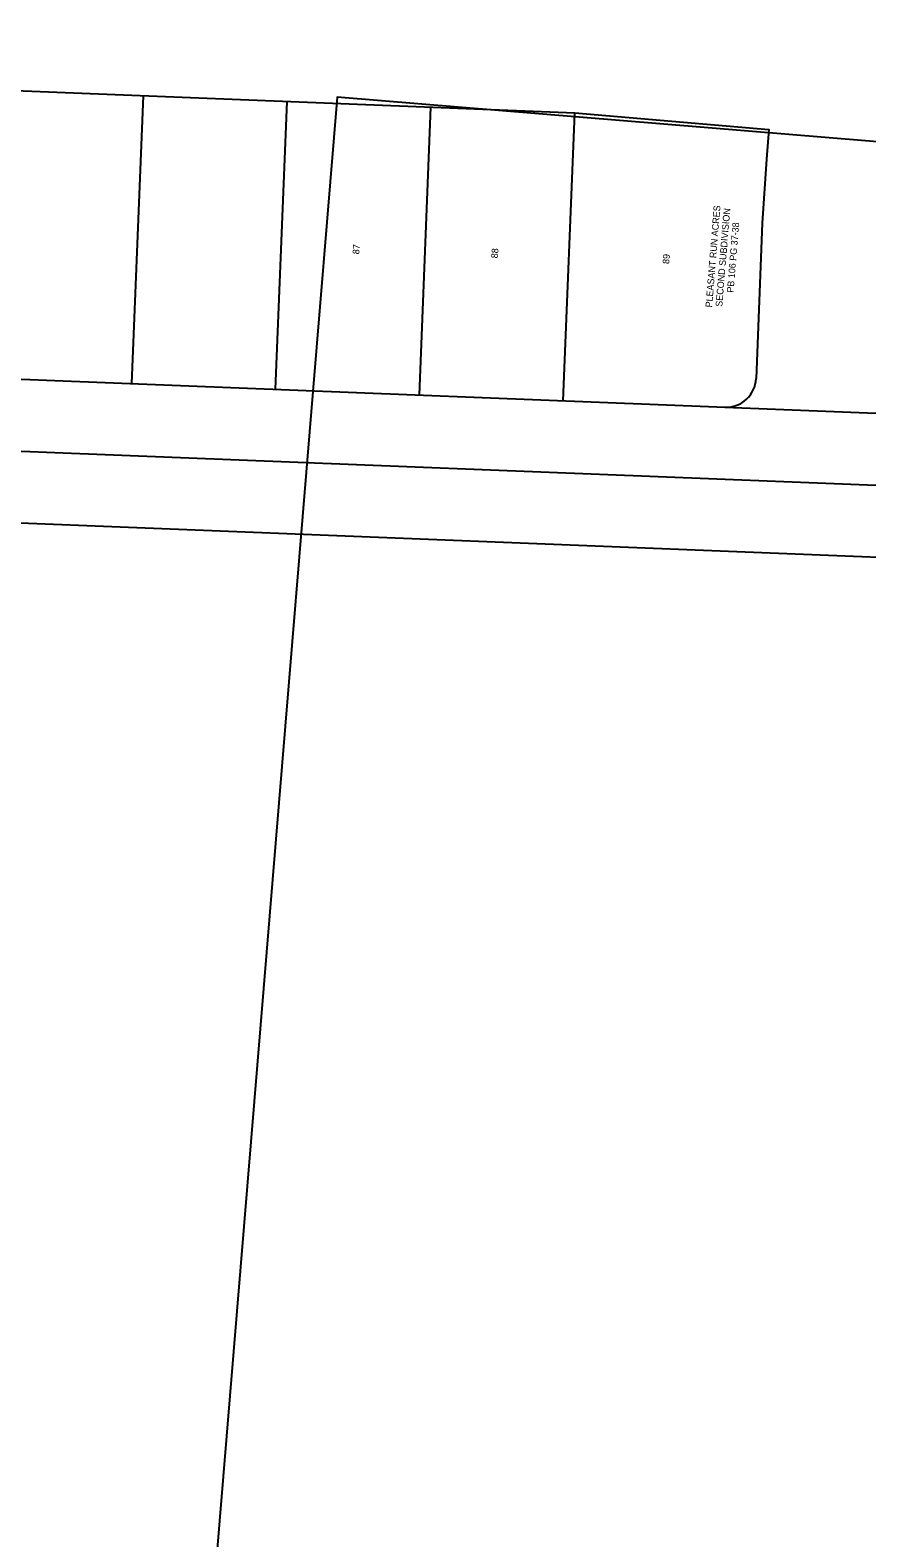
# Model space of a CAD drawing. Extents: x 1379776 to 1382941, y 467490 to 471592.
# Drawn here: x 1381007 to 1381356, y 469835 to 470463 of the extents above; entities that cross this region are included whole.
import ezdxf

# ---------------------------------------------------------------- set-up
doc = ezdxf.new("R2010")
doc.units = 0
for name, color, linetype in [('PV_P_Drive', 7, 'Continuous'), ('PV_X_Driveway', 7, 'Continuous'), ('RC_X_Text', 7, 'Continuous'), ('RD_X_Wall', 7, 'Continuous'), ('SH_Named_Boundary', 7, 'Continuous'), ('SV_X_Break_Lines', 7, 'Continuous')]:
    doc.layers.add(name, color=color, linetype=linetype)

msp = doc.modelspace()

# ---------------------------------------------------------------- linework, layer by layer
at = {"layer": 'PV_P_Drive'}
msp.add_line((1380559.29, 470305.26), (1381622.42, 470262.79), dxfattribs=at)
msp.add_lwpolyline([(1380244.81, 470361.47), (1380249.52, 470458.85), (1380334.42, 470454.75), (1380369.86, 470462.95), (1381233.96, 470428.43), (1381314.91, 470421.56), (1381313.86, 470409.15), (1381312.19, 470382.46), (1381309.61, 470317.82)], dxfattribs=at)
msp.add_arc((1381297.12, 470318.32), 12.5, 267.71231, 357.71231, dxfattribs=at)
at = {"layer": 'PV_X_Driveway'}
msp.add_lwpolyline([(1381481.91, 468926.74), (1381589.94, 470234.06), (1380557.84, 470275.29)], dxfattribs=at)
at = {"layer": 'RD_X_Wall'}
msp.add_line((1380560.49, 470335.24), (1381583.03, 470294.39), dxfattribs=at)
at = {"layer": 'SH_Named_Boundary'}
msp.add_lwpolyline([(1381019.66, 469039.84), (1381836.87, 468972.31), (1381848.4, 469111.83), (1381859.93, 469251.36), (1381871.46, 469390.88), (1381882.99, 469530.4), (1381894.52, 469669.93), (1381906.05, 469809.45), (1381917.58, 469948.98), (1381929.11, 470088.5), (1381940.64, 470228.03), (1381952.16, 470367.55), (1381134.95, 470435.08), (1381123.42, 470295.56), (1381111.89, 470156.03), (1381100.36, 470016.51), (1381088.83, 469876.98), (1381077.3, 469737.46), (1381065.77, 469597.93), (1381054.24, 469458.41), (1381042.71, 469318.88), (1381031.19, 469179.36)], close=True, dxfattribs=at)
at = {"layer": 'SV_X_Break_Lines'}
for p, q in [((1381049.32, 470315.71), (1381054.11, 470435.61)), ((1381109.27, 470313.31), (1381114.06, 470433.22)), ((1381169.22, 470310.92), (1381174.01, 470430.82)), ((1381229.17, 470308.52), (1381233.96, 470428.43))]:
    msp.add_line(p, q, dxfattribs=at)

# ---------------------------------------------------------------- texts
at = {"layer": 'RC_X_Text'}
for s, p in [('PLEASANT RUN ACRES', (1381291.23, 470347.3)), ('SECOND SUBDIVISION', (1381295.47, 470347.59)), ('PB 106 PG 37-38', (1381300.17, 470353.46)), ('87', (1381144.09, 470369.45)), ('88', (1381201.86, 470367.78)), ('89', (1381273.34, 470365.4))]:
    msp.add_text(s, height=2.8, rotation=85.27618, dxfattribs=at).set_placement(p)

doc.saveas('drawing.dxf')
